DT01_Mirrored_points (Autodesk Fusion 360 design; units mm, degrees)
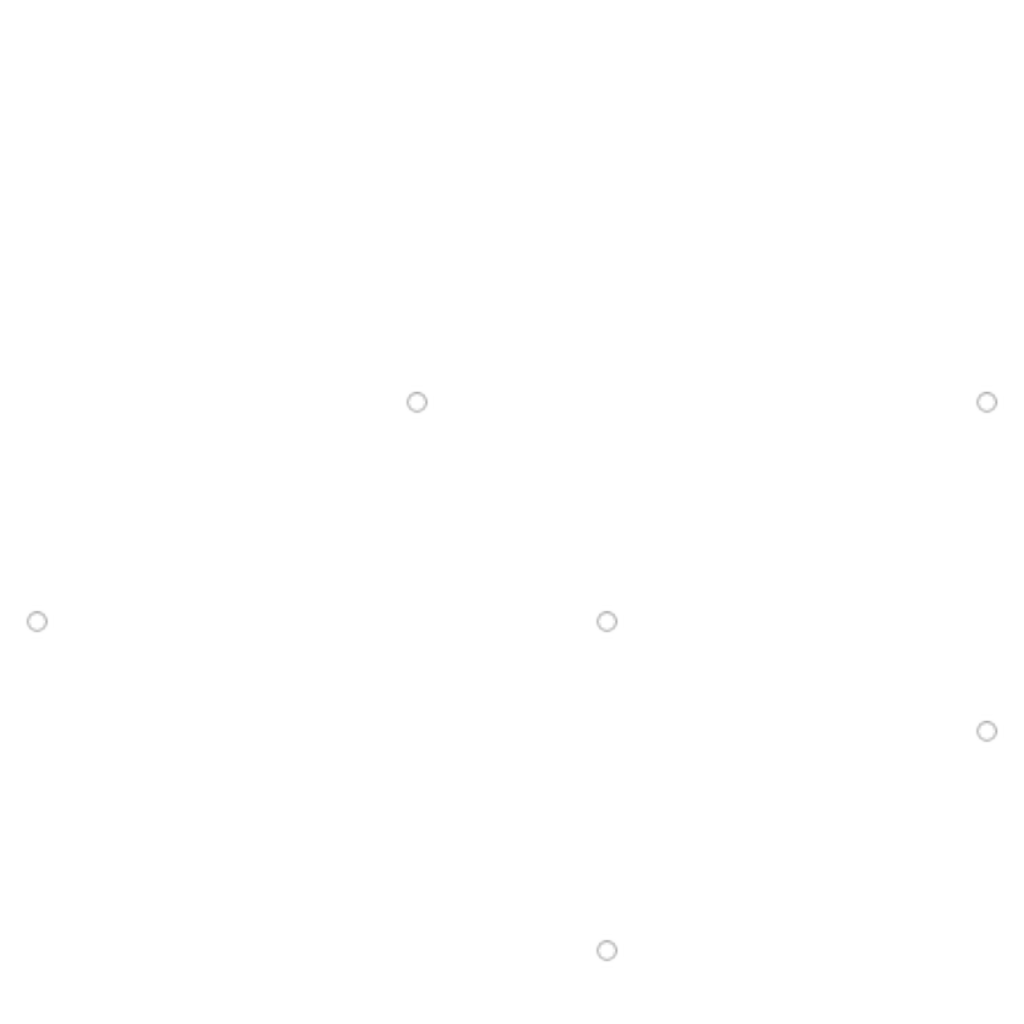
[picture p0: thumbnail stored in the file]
part number: 2026-10-26-12-17-31-515
sketch "Tube points" plane through (0, 0, 0) normal (0, 0, 1) x axis (1, 0, 0)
